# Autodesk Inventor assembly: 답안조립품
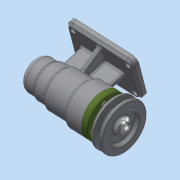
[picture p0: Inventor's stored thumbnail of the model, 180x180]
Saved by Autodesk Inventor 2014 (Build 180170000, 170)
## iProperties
Created: 2016-06
Part Number: 답안조립품
Document SubType Name: Assembly
Designer: SCD-A15
Author: SCD-A15
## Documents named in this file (12)
- C:\Users\SCD-A15\Desktop\460607V1025\답안조립품.iam
- C:\Users\SCD-A15\Desktop\460607V1025\본체.ipt
- C:\Users\SCD-A15\Desktop\460607V1025\축.ipt
- C:\Users\SCD-A15\Desktop\460607V1025\베어링 6004.ipt
- C:\Users\SCD-A15\Desktop\460607V1025\어댑터슬리브.ipt
- C:\Users\SCD-A15\Desktop\460607V1025\베어링 51202.ipt
- C:\Users\SCD-A15\Desktop\460607V1025\커버.ipt
- C:\Users\SCD-A15\Desktop\460607V1025\키 5 x 5 x 16.ipt
- C:\Users\SCD-A15\Desktop\460607V1025\V벨트풀리.ipt
- C:\Users\SCD-A15\Desktop\460607V1025\오일 실.ipt
- C:\Users\SCD-A15\Desktop\460607V1025\볼트 M4 x 12.ipt
- C:\Users\SCD-A15\Desktop\460607V1025\멈춤나사 M3x8.ipt
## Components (6 placed, 2 different names)
1. V벨트풀리:1
2. ISO 4762 M4 x 12:5
3. ISO 4762 M4 x 12:1
4. ISO 4762 M4 x 12:2
5. ISO 4762 M4 x 12:3
6. ISO 4762 M4 x 12:4
